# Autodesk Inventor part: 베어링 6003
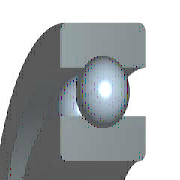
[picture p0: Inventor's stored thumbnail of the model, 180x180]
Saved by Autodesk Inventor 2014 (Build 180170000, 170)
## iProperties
IsCustomPart: 1
Company: 한국ATC센터
Created: 2014-07
Part Number: 베어링 6003
Material: 강, 연강
Description: 깊은 그루브 볼 베어링
Document SubType Name: Modeling
Standard: KS B 2023
Designer: KYOUNG IL JANG
Standards Organization: KS
Language: ko-KR
Size Designation: 6003 - 17 x 35 x 10
Categories: <MemberInstance><Categories><Category DisplayName="샤프트 부품" InternalName="7f7aeb1f-a693-4053-b835-cee3144e0d98" Mnemonic="SHFT"><Category DisplayName="베어링" Inter
Density: 1 g/cm^3
Appearance: 강철
Author: KYOUNG IL JANG
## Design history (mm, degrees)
sketch "스케치" dims "d0" = 4.68 (= -0.26 x WD + 0.26 x BD)
  geometry: L1 (2.66, 13)-(7.34, 13); L2 (5, 13)-(5, 10.66); L3 (5, 13)-(5, 15.34); L4 (3.261, 11.434)-(0, 11.434); L5 (0, 8.5)-(10, 8.5); L6 (3.261, 14.566)-(0, 14.566); L7 (0, 17.5)-(10, 17.5); L8 (10, 8.5)-(10, 11.434); L9 (6.739, 11.434)-(10, 11.434); L10 (6.739, 14.566)-(10, 14.566); L11 (10, 17.5)-(10, 14.566); L12 (-1.4, 0)-(8.4, 0) reference; L13 (0, -0.3)-(0, 5.3) reference
  constraints: 22 end point, 4 point on line, 2 collinear, 2 perpendicular, 2 symmetric about line, 1 midpoint, 1 parallel, 14 other
  dimensions: "d9" = 17 diameter of L5 L12 (= WD); "d11" = 35 diameter of L7 L12 (= BD); "d12" = 10 distance between parallel lines of L8 L13 (= KB); "d13" = 22.868 diameter of L9 L12 (= 0.326 x BD + 0.674 x WD)
revolve "본체" stored, may be unused: angle "d6" = 90 deg
revolve "볼" stored, may be unused: angle "d7" = 90 deg
pattern_circular "IDS_ARRAYBALL[SIMPL:T]" dims angle "d3" = 360 deg
body "Solid1"
fillet "모깎기1" dims "d1" = 0.3 (= KRS)
other parameters: "WD" = 17 [user parameter; used in 5 equation terms], "BD" = 35 [user parameter; used in 5 equation terms], "KB" = 10 [user parameter; used in 1 equation term], "KRS" = 0.3 [user parameter; used in 1 equation term], "d4" = 0, "d5" = 0, "d8" = 0, "d14" = 0, "d15" = 0, "BBA" = 0 [user parameter], "BC0" = 3250000 [user parameter], "BC" = 6050000 [user parameter], "BR" = 17.5 (= 0.5 x BD) [user parameter], "WR" = 8.5 (= 0.5 x WD) [user parameter]
